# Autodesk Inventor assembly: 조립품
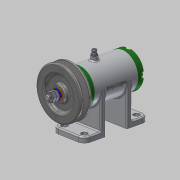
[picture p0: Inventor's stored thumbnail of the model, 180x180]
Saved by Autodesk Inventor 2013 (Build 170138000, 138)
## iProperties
Created: 2017-02
Part Number: 조립품
Document SubType Name: Assembly
Designer: Administrator
Author: Administrator
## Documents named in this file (16)
- C:\Users\Administrator\Desktop\470207V1003\조립품.iam
- C:\Users\Administrator\Desktop\470207V1003\470207V1003\V벨트풀리.ipt
- C:\Users\Administrator\Desktop\470207V1003\470207V1003\너트 M 8.ipt
- C:\Users\Administrator\Desktop\470207V1003\470207V1003\니플 M 6 x 0.75.ipt
- C:\Users\Administrator\Desktop\470207V1003\470207V1003\뒤커버.ipt
- C:\Users\Administrator\Desktop\470207V1003\470207V1003\베어링 15 x 32 x 9.ipt
- C:\Users\Administrator\Desktop\470207V1003\470207V1003\볼트 M 6 x 8.ipt
- C:\Users\Administrator\Desktop\470207V1003\470207V1003\볼트 M4 x 12.ipt
- C:\Users\Administrator\Desktop\470207V1003\470207V1003\스프링와셔 8.ipt
- C:\Users\Administrator\Desktop\470207V1003\470207V1003\앞커버.ipt
- C:\Users\Administrator\Desktop\470207V1003\470207V1003\오일 실 15 25 7.ipt
- C:\Users\Administrator\Desktop\470207V1003\470207V1003\와셔 6x11.5.ipt
- C:\Users\Administrator\Desktop\470207V1003\470207V1003\와셔 8x17.ipt
- C:\Users\Administrator\Desktop\470207V1003\470207V1003\축.ipt
- C:\Users\Administrator\Desktop\470207V1003\470207V1003\키 3 x 3 x 12.ipt
- C:\Users\Administrator\Desktop\470207V1003\본체.ipt
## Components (11 placed, 3 different names)
1. V벨트풀리:1
2. KS B 2023 6002 - 15 x 32 x 9:1
3. ISO 4762 M4 x 12:1
4. KS B 2023 6002 - 15 x 32 x 9:2
5. ISO 4762 M4 x 12:2
6. ISO 4762 M4 x 12:3
7. ISO 4762 M4 x 12:4
8. ISO 4762 M4 x 12:5
9. ISO 4762 M4 x 12:6
10. ISO 4762 M4 x 12:7
11. ISO 4762 M4 x 12:8
